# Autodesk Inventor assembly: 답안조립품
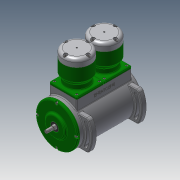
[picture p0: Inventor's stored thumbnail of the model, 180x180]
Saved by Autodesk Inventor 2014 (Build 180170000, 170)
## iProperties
Created: 2017-08
Part Number: 답안조립품
Document SubType Name: Assembly
Designer: user
Author: user
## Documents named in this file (16)
- C:\Users\user\Desktop\370808V1004\답안조립품.iam
- C:\Users\user\Desktop\370808V1004\본체.ipt
- C:\Users\user\Desktop\370808V1004\너트 M4.ipt
- C:\Users\user\Desktop\370808V1004\베어링 12 x 28 x 8.ipt
- C:\Users\user\Desktop\370808V1004\볼트 M4 x 8.ipt
- C:\Users\user\Desktop\370808V1004\볼트 M5 x 20.ipt
- C:\Users\user\Desktop\370808V1004\실린더.ipt
- C:\Users\user\Desktop\370808V1004\실린더헤드.ipt
- C:\Users\user\Desktop\370808V1004\앞커버.ipt
- C:\Users\user\Desktop\370808V1004\오일 실 12 25 7.ipt
- C:\Users\user\Desktop\370808V1004\육각 머리 볼트 M4 x 16.ipt
- C:\Users\user\Desktop\370808V1004\커넥팅로드 엔드.ipt
- C:\Users\user\Desktop\370808V1004\커넥팅로드.ipt
- C:\Users\user\Desktop\370808V1004\크랭크축.ipt
- C:\Users\user\Desktop\370808V1004\피스톤.ipt
- C:\Users\user\Desktop\370808V1004\피스톤핀.ipt
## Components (4 placed, 2 different names)
1. 피스톤:1
2. 피스톤핀:1
3. 피스톤:2
4. 피스톤핀:2
## Named parameters: d20_d19 = 0, d29_d23 = 0, d30_d24 = 0, d31_d25 = 0, d32_d26 = 0, d33_d10 = 0, d34_d11 = 0, d35_d12 = 0, d36_d13 = 0, d37_d14 = 0, d38_d15 = 0, d39_d16 = 0, d40_d17 = 0, d41_d18 = 0, d42_d19 = 0, d43_d20_d19 = 0, d44_d21 = 0, d45_d22 = 0, d46_d8 = 0, d47_d9 = 0
